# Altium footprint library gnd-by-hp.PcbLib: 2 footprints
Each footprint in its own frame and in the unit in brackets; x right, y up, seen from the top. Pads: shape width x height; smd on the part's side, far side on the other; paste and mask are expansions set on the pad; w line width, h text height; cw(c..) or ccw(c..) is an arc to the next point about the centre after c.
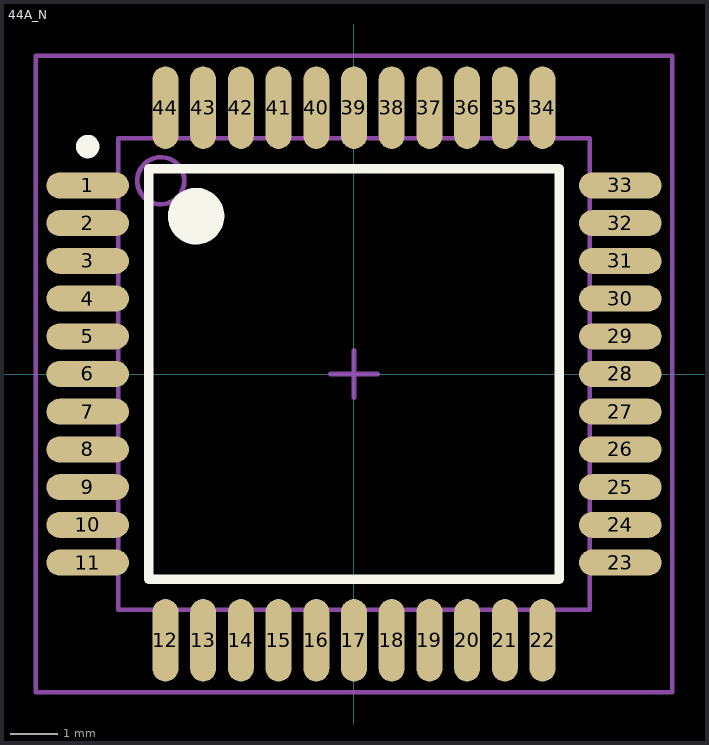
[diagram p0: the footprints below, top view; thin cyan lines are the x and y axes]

## 44A_N [mm] "Thin QFP, 44-Leads, Body 10x10mm, Pitch 0.8mm, IPC Medium Density"
height 1.2
pads (44):
  oval 1.75x0.55 smd: 1(-5.65,4) 2(-5.65,3.2) 3(-5.65,2.4) 4(-5.65,1.6) 5(-5.65,0.8) 6(-5.65,0) 7(-5.65,-0.8) 8(-5.65,-1.6) 9(-5.65,-2.4) 10(-5.65,-3.2) 11(-5.65,-4) 23(5.65,-4) 24(5.65,-3.2) 25(5.65,-2.4) 26(5.65,-1.6) 27(5.65,-0.8) 28(5.65,0) 29(5.65,0.8) 30(5.65,1.6) 31(5.65,2.4) 32(5.65,3.2) 33(5.65,4)
  oval 0.55x1.75 smd: 12(-4,-5.65) 13(-3.2,-5.65) 14(-2.4,-5.65) 15(-1.6,-5.65) 16(-0.8,-5.65) 17(0,-5.65) 18(0.8,-5.65) 19(1.6,-5.65) 20(2.4,-5.65) 21(3.2,-5.65) 22(4,-5.65) 34(4,5.65) 35(3.2,5.65) 36(2.4,5.65) 37(1.6,5.65) 38(0.8,5.65) 39(0,5.65) 40(-0.8,5.65) 41(-1.6,5.65) 42(-2.4,5.65) 43(-3.2,5.65) 44(-4,5.65)
Top Overlay:
  circle w0.6: c-3.35,3.35 r0.3
  circle w0.25: c-5.65,4.825 r0.125
  lines w0.2: -4.35,-4.35 4.35,-4.35 4.35,4.35 -4.35,4.35 -4.35,-4.35
Mechanical 13:
  circle w0.1: c-4.1,4.1 r0.5
  lines w0.1: -5,-5 5,-5 5,5 -5,5 -5,-5
Mechanical 15:
  lines w0.1: -0.5,0 0.5,0 ; 0,-0.5 0,0.5 ; -6.75,-6.75 6.75,-6.75 6.75,6.75 -6.75,6.75 -6.75,-6.75
3D body: height 1.2, standoff 0, extent -5,-5 5,5

## PCBComponent_1 [mm]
